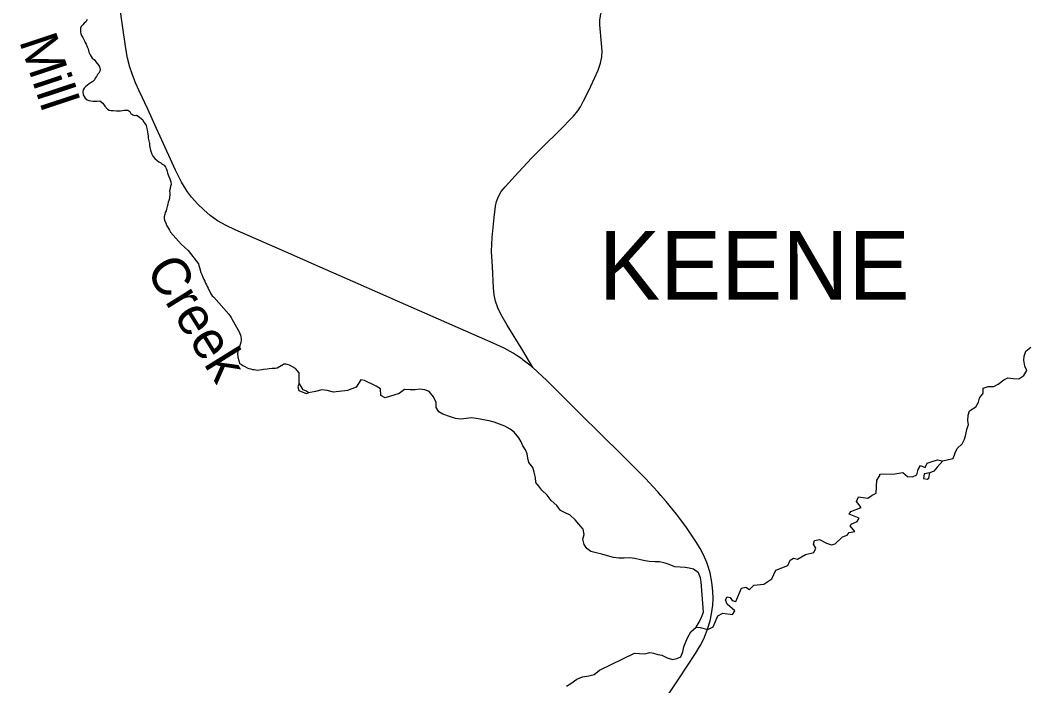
# Model space of a CAD drawing. Extents: x -6.3 to 34, y 0 to 22.
# Drawn here: x 5.76 to 7.479, y 14.392 to 15.527 of the extents above; entities that cross this region are included whole.
import ezdxf

# ---------------------------------------------------------------- set-up
doc = ezdxf.new("R2010")
doc.units = 0
for name, color, linetype in [('GM_X_Minor_Lake', 7, 'Continuous'), ('GM_X_Minor_River', 7, 'Continuous'), ('GM_X_Minor_River_Text', 7, 'Continuous'), ('GM_X_State_Route', 7, 'Continuous'), ('GM_X_Township_Text', 7, 'Continuous')]:
    doc.layers.add(name, color=color, linetype=linetype)

msp = doc.modelspace()

# ---------------------------------------------------------------- linework, layer by layer
at = {"layer": 'GM_X_Minor_Lake'}
for points in [[(6.2354, 14.9083), (6.2329, 14.9023), (6.2346, 14.8961), (6.2473, 14.891)], [(6.2354, 14.9083), (6.2329, 14.9023), (6.2346, 14.8961), (6.2473, 14.891), (6.2513, 14.8919), (6.2481, 14.8947), (6.2423, 14.8969), (6.2354, 14.9083)], [(6.2473, 14.891), (6.2513, 14.8919), (6.2481, 14.8947), (6.2423, 14.8969), (6.2354, 14.9083)], [(7.2996, 14.7457), (7.3056, 14.7445), (7.3084, 14.7463), (7.3102, 14.7553)], [(7.3102, 14.7553), (7.3008, 14.754), (7.2996, 14.7457)]]:
    msp.add_lwpolyline(points, dxfattribs=at)
at = {"layer": 'GM_X_Minor_River'}
for points in [[(5.8742, 15.5285), (5.8716, 15.5248), (5.8688, 15.5225), (5.8667, 15.5196), (5.8641, 15.5165), (5.8626, 15.5136), (5.8626, 15.511), (5.8629, 15.5074), (5.8634, 15.5043), (5.8647, 15.5011), (5.8668, 15.4978), (5.8694, 15.4921), (5.871, 15.4892), (5.8723, 15.4864), (5.8741, 15.4817), (5.8757, 15.4783), (5.8768, 15.4731), (5.8791, 15.468), (5.8825, 15.4628), (5.8859, 15.4602), (5.8888, 15.4566), (5.8914, 15.4537), (5.8948, 15.4493), (5.8958, 15.4462), (5.8961, 15.4431), (5.8956, 15.4405), (5.8938, 15.4371), (5.892, 15.4345), (5.8899, 15.4311), (5.8879, 15.4283), (5.8866, 15.4257), (5.8838, 15.423), (5.8809, 15.4212), (5.8778, 15.4186), (5.8747, 15.4165), (5.8719, 15.4144), (5.8688, 15.4113), (5.8673, 15.4084), (5.8665, 15.4056)], [(5.8665, 15.4056), (5.8675, 15.3999), (5.8689, 15.397), (5.8707, 15.3942), (5.8741, 15.3918), (5.8772, 15.3903), (5.8803, 15.39), (5.8842, 15.3893), (5.887, 15.3893), (5.8909, 15.389), (5.8956, 15.3896), (5.901, 15.3857), (5.9042, 15.3805), (5.9088, 15.3756), (5.9117, 15.3738), (5.9148, 15.3733), (5.9184, 15.3736), (5.9244, 15.3728), (5.928, 15.3726), (5.9311, 15.3726), (5.9345, 15.3736), (5.9376, 15.3739), (5.9433, 15.3737), (5.9467, 15.3714), (5.9488, 15.3682), (5.9519, 15.3662), (5.9552, 15.3649), (5.9581, 15.3652), (5.9612, 15.3639), (5.9664, 15.3598), (5.969, 15.3572), (5.9703, 15.3543), (5.9732, 15.3509), (5.9747, 15.3481), (5.9755, 15.345), (5.9763, 15.3403), (5.9771, 15.3367), (5.9774, 15.3333), (5.9779, 15.3297), (5.9782, 15.326), (5.979, 15.3219), (5.9801, 15.3172), (5.9806, 15.3144), (5.9811, 15.3105), (5.9822, 15.3055), (5.9832, 15.3024), (5.9846, 15.299), (5.9861, 15.2957), (5.9893, 15.2913), (5.9934, 15.2879), (5.9963, 15.2859), (5.9994, 15.284), (6.0022, 15.2817), (6.0051, 15.2799), (6.0075, 15.2768), (6.0095, 15.2734), (6.0106, 15.2698), (6.0111, 15.2667), (6.0124, 15.2638), (6.0132, 15.261), (6.0153, 15.2566), (6.0166, 15.2519), (6.0172, 15.247), (6.0164, 15.2441), (6.0154, 15.2402), (6.0146, 15.2363), (6.0149, 15.2316), (6.0149, 15.229), (6.0147, 15.2262), (6.0142, 15.2231), (6.0134, 15.2199), (6.0124, 15.2168), (6.0116, 15.2134), (6.0106, 15.2095), (6.0093, 15.2054), (6.0086, 15.2023), (6.0068, 15.1997), (6.0063, 15.1963), (6.0055, 15.1921), (6.0055, 15.1893), (6.0058, 15.1864), (6.0082, 15.1812), (6.0095, 15.1779), (6.0108, 15.175), (6.0144, 15.1693), (6.0163, 15.1659), (6.0342, 15.1455), (6.0465, 15.1346), (6.0637, 15.1121), (6.0644, 15.109), (6.0655, 15.1059), (6.0681, 15.0971), (6.0694, 15.0939), (6.0713, 15.089), (6.0731, 15.0851), (6.0744, 15.0823), (6.076, 15.0792), (6.0773, 15.0763), (6.0786, 15.0732), (6.0802, 15.0703), (6.0849, 15.061)], [(6.0849, 15.061), (6.0872, 15.0574), (6.0901, 15.0551), (6.1158, 15.0263), (6.1195, 15.0206), (6.1213, 15.017), (6.1331, 14.996), (6.1346, 14.9932), (6.1357, 14.9901), (6.136, 14.9875), (6.1365, 14.9838), (6.1365, 14.981), (6.1363, 14.9779), (6.135, 14.9742), (6.1335, 14.9703), (6.1319, 14.9677), (6.1317, 14.9648), (6.1309, 14.9617), (6.1304, 14.9591), (6.131, 14.9529), (6.1325, 14.9472), (6.1339, 14.942), (6.137, 14.9402), (6.1396, 14.9386), (6.1429, 14.9368), (6.1471, 14.9348), (6.1499, 14.9335), (6.1528, 14.9327), (6.1559, 14.9317), (6.1588, 14.9317), (6.1642, 14.9304), (6.172, 14.9315), (6.1748, 14.9323), (6.1808, 14.9328), (6.1841, 14.9336), (6.1896, 14.9342), (6.1947, 14.9342), (6.1978, 14.9345), (6.2086, 14.9409)], [(7.2248, 14.7534), (7.2506, 14.7536), (7.2576, 14.7549), (7.2643, 14.7562), (7.2721, 14.7492), (7.2806, 14.7487), (7.2881, 14.7521), (7.2905, 14.7612), (7.2943, 14.768), (7.3021, 14.7644), (7.3057, 14.7722), (7.314, 14.7751), (7.3231, 14.7777), (7.3316, 14.7762), (7.3503, 14.7801), (7.3536, 14.7895), (7.3567, 14.7968), (7.3652, 14.8051), (7.3696, 14.8129), (7.3717, 14.8212), (7.3732, 14.8296), (7.376, 14.8379), (7.375, 14.8444), (7.3755, 14.8537), (7.378, 14.8613), (7.3886, 14.8681), (7.3933, 14.8761), (7.3951, 14.8829), (7.401, 14.8915), (7.4012, 14.8998), (7.4098, 14.9027), (7.4191, 14.903), (7.4269, 14.9069), (7.4364, 14.9142), (7.4432, 14.9173), (7.4522, 14.9166), (7.4618, 14.9158), (7.4706, 14.9216), (7.4758, 14.9302), (7.4721, 14.9372), (7.4703, 14.9478), (7.4708, 14.9546), (7.4741, 14.9629), (7.4827, 14.9697)], [(6.2354, 14.9083), (6.2352, 14.9162), (6.2356, 14.9261), (6.2291, 14.9336), (6.219, 14.9393), (6.2125, 14.9411), (6.2086, 14.9409)], [(6.4147, 14.8978), (6.4056, 14.8907), (6.382, 14.8834), (6.3748, 14.8873), (6.3739, 14.8987), (6.3669, 14.9036), (6.3466, 14.9129), (6.3407, 14.914), (6.3327, 14.9015), (6.3179, 14.8957), (6.2941, 14.8933), (6.2832, 14.8961), (6.2741, 14.8972), (6.2635, 14.8943), (6.2513, 14.8919)], [(6.8846, 14.5945), (6.8755, 14.5952), (6.8662, 14.5994), (6.8592, 14.6014), (6.8496, 14.6037), (6.8418, 14.604), (6.8322, 14.6042), (6.8254, 14.6053), (6.8169, 14.6071), (6.8075, 14.6094), (6.7987, 14.6109), (6.7896, 14.6099), (6.78, 14.6101), (6.7712, 14.6114), (6.7608, 14.6142), (6.751, 14.617), (6.7416, 14.6191), (6.7328, 14.6217), (6.7255, 14.6266), (6.7211, 14.6331), (6.7189, 14.6422), (6.7212, 14.6505), (6.7197, 14.6596), (6.7118, 14.668), (6.7061, 14.6752), (6.6972, 14.6833), (6.6887, 14.6874), (6.6806, 14.6913), (6.6744, 14.6999), (6.665, 14.7082), (6.6579, 14.7175), (6.6493, 14.7261), (6.6439, 14.7328), (6.6389, 14.7393), (6.6384, 14.7479), (6.6362, 14.7568), (6.6339, 14.7648), (6.6266, 14.7731), (6.625, 14.7807), (6.6242, 14.7882), (6.6213, 14.7947), (6.6169, 14.8017), (6.6137, 14.8082), (6.6101, 14.8155), (6.6017, 14.8248), (6.595, 14.83), (6.5861, 14.8352), (6.577, 14.8388), (6.5679, 14.8419), (6.5591, 14.844), (6.5523, 14.8455), (6.544, 14.8471), (6.5373, 14.8484), (6.529, 14.8491), (6.5199, 14.8483), (6.5108, 14.8473), (6.5018, 14.8485), (6.4934, 14.8511), (6.4805, 14.8558), (6.4734, 14.8597), (6.469, 14.8667), (6.469, 14.8755), (6.4645, 14.8851), (6.4572, 14.894), (6.4497, 14.8973), (6.4406, 14.8983), (6.4331, 14.897), (6.4245, 14.897), (6.4147, 14.8978)], [(7.3323, 14.7763), (7.3229, 14.7653), (7.317, 14.7582), (7.3102, 14.7553)], [(6.9122, 14.4925), (6.9187, 14.492), (6.9317, 14.4882), (6.941, 14.4929), (6.9492, 14.5116), (6.9577, 14.5161), (6.9741, 14.5143), (6.9782, 14.5203), (6.9647, 14.5314), (6.9618, 14.5392), (6.9649, 14.5439), (6.9698, 14.5432), (6.9732, 14.5377), (6.9797, 14.5364), (6.9892, 14.5591), (6.9965, 14.5609), (7.0027, 14.5568), (7.0105, 14.5638), (7.0271, 14.5657), (7.041, 14.5748), (7.048, 14.5894), (7.0682, 14.5975), (7.0725, 14.6069), (7.0777, 14.6098), (7.0845, 14.6082), (7.0982, 14.6166), (7.1124, 14.62), (7.1158, 14.6273), (7.1121, 14.6338), (7.1136, 14.64), (7.1222, 14.6419), (7.1341, 14.6356), (7.1427, 14.6328), (7.1492, 14.6344), (7.1616, 14.6464), (7.1696, 14.6495), (7.173, 14.6539), (7.1826, 14.6555), (7.1747, 14.6651), (7.1771, 14.6688), (7.1864, 14.6727), (7.1897, 14.6784), (7.1726, 14.6852), (7.1754, 14.6896), (7.193, 14.6967), (7.1852, 14.7065), (7.1888, 14.7146), (7.2046, 14.7123), (7.2119, 14.7173), (7.2191, 14.7209), (7.2201, 14.7433), (7.2252, 14.7511), (7.2248, 14.7534)], [(6.6912, 14.3921), (6.6982, 14.3963), (6.7088, 14.4036), (6.7186, 14.4075), (6.7292, 14.4094), (6.7383, 14.412), (6.7471, 14.419), (6.8072, 14.4481), (6.8157, 14.4476), (6.8248, 14.4471), (6.8331, 14.4494), (6.8396, 14.4479), (6.8466, 14.4458), (6.8536, 14.4445), (6.8624, 14.4404), (6.8715, 14.4375), (6.879, 14.4391), (6.886, 14.4417), (6.8891, 14.4501), (6.8911, 14.4587), (6.8947, 14.4673), (6.8981, 14.4756), (6.9032, 14.4844), (6.912, 14.4923), (6.9172, 14.5011), (6.921, 14.5097), (6.9244, 14.5178), (6.9203, 14.5698), (6.9195, 14.5766), (6.9158, 14.5849), (6.9075, 14.5914), (6.9002, 14.5929), (6.8934, 14.5942), (6.8846, 14.5945)], [(6.6912, 14.3921), (6.6982, 14.3963), (6.7088, 14.4036), (6.7186, 14.4075), (6.7292, 14.4094), (6.7383, 14.412), (6.7471, 14.419), (6.8072, 14.4481), (6.8157, 14.4476), (6.8248, 14.4471), (6.8331, 14.4494), (6.8396, 14.4479), (6.8466, 14.4458), (6.8536, 14.4445), (6.8624, 14.4404), (6.8715, 14.4375), (6.879, 14.4391), (6.886, 14.4417), (6.8891, 14.4501), (6.8911, 14.4587), (6.8947, 14.4673), (6.8981, 14.4756), (6.9032, 14.4844), (6.912, 14.4923), (6.9172, 14.5011), (6.921, 14.5097), (6.9244, 14.5178), (6.9203, 14.5698), (6.9195, 14.5766), (6.9158, 14.5849), (6.9075, 14.5914), (6.9002, 14.5929), (6.8934, 14.5942), (6.8846, 14.5945)]]:
    msp.add_lwpolyline(points, dxfattribs=at)
at = {"layer": 'GM_X_State_Route'}
for points in [[(6.7221, 15.3936), (6.7325, 15.4146), (6.7449, 15.4423), (6.7488, 15.4538), (6.7512, 15.4648), (6.7518, 15.4745), (6.7509, 15.4877), (6.748, 15.5194), (6.7481, 15.5273), (6.7489, 15.5348), (6.7505, 15.5427), (6.7537, 15.5525), (6.758, 15.5633), (6.7624, 15.5732), (6.7674, 15.5829), (6.7739, 15.5938), (6.7787, 15.6022), (6.7895, 15.6153), (6.8239, 15.6571), (6.8479, 15.6878), (6.8524, 15.6938)], [(6.0451, 15.2347), (6.0421, 15.2394), (6.0349, 15.251), (6.0248, 15.2716), (5.9988, 15.3288), (5.9921, 15.3429), (5.9773, 15.3757), (5.963, 15.4067), (5.9567, 15.4203), (5.9506, 15.436), (5.947, 15.4471), (5.9431, 15.4624), (5.9402, 15.4793), (5.9282, 15.562)], [(6.5795, 15.2352), (6.5863, 15.2431), (6.609, 15.2684), (6.6322, 15.2928), (6.6515, 15.3121), (6.6784, 15.3388), (6.7029, 15.3635), (6.7104, 15.3727), (6.7148, 15.3797), (6.7202, 15.3897), (6.7221, 15.3936)], [(6.6338, 14.935), (6.6261, 14.941), (6.6174, 14.9478), (6.6147, 14.9497), (6.6084, 14.9542), (6.6002, 14.9594), (6.5849, 14.9682), (6.5662, 14.9766), (6.487, 15.0114), (6.4028, 15.0485), (6.3358, 15.0779), (6.2714, 15.1061), (6.2121, 15.1322), (6.1667, 15.1525), (6.1264, 15.1698), (6.111, 15.1771), (6.0964, 15.1855), (6.0837, 15.1944), (6.0727, 15.2039), (6.0627, 15.2136), (6.0517, 15.2258), (6.0451, 15.2347)], [(6.6338, 14.935), (6.6167, 14.9639), (6.59, 15.0075), (6.5791, 15.0259), (6.5742, 15.0368), (6.5699, 15.0485), (6.568, 15.0592), (6.5669, 15.0711), (6.5647, 15.1074), (6.5634, 15.1327), (6.5636, 15.1453), (6.5643, 15.1569), (6.568, 15.1908), (6.5701, 15.2104), (6.572, 15.2182), (6.5749, 15.2266), (6.5795, 15.2352)], [(6.9314, 14.5991), (6.9303, 14.6029), (6.9245, 14.6159), (6.9191, 14.6263), (6.9128, 14.6366), (6.8942, 14.6638), (6.8784, 14.685), (6.8608, 14.7067), (6.8517, 14.7172), (6.8472, 14.7224), (6.8388, 14.7318), (6.8255, 14.7459), (6.7914, 14.7802), (6.7426, 14.8282), (6.7208, 14.8499), (6.6831, 14.8873), (6.6573, 14.9128), (6.6338, 14.935)], [(6.9281, 14.48), (6.9313, 14.489), (6.9357, 14.5034), (6.9383, 14.5153), (6.9403, 14.5298), (6.9408, 14.541), (6.9406, 14.5539), (6.9389, 14.5694), (6.9357, 14.5851), (6.9314, 14.5991)], [(6.841, 14.3426), (6.8827, 14.4041), (6.9107, 14.4474), (6.9192, 14.4616), (6.925, 14.4728), (6.9281, 14.48)]]:
    msp.add_lwpolyline(points, dxfattribs=at)

# ---------------------------------------------------------------- texts
at = {"layer": 'GM_X_Minor_River_Text'}
for s, rotation, p in [('Mill', 288.3458, (5.7577, 15.4921)), ('Creek', 301.8625, (5.9726, 15.1013))]:
    msp.add_text(s, height=0.0649, rotation=rotation, dxfattribs=at).set_placement(p)
at = {"layer": 'GM_X_Township_Text'}
msp.add_text('KEENE', height=0.11682, rotation=0, dxfattribs=at).set_placement((6.7464, 15.0509))

doc.saveas('drawing.dxf')
